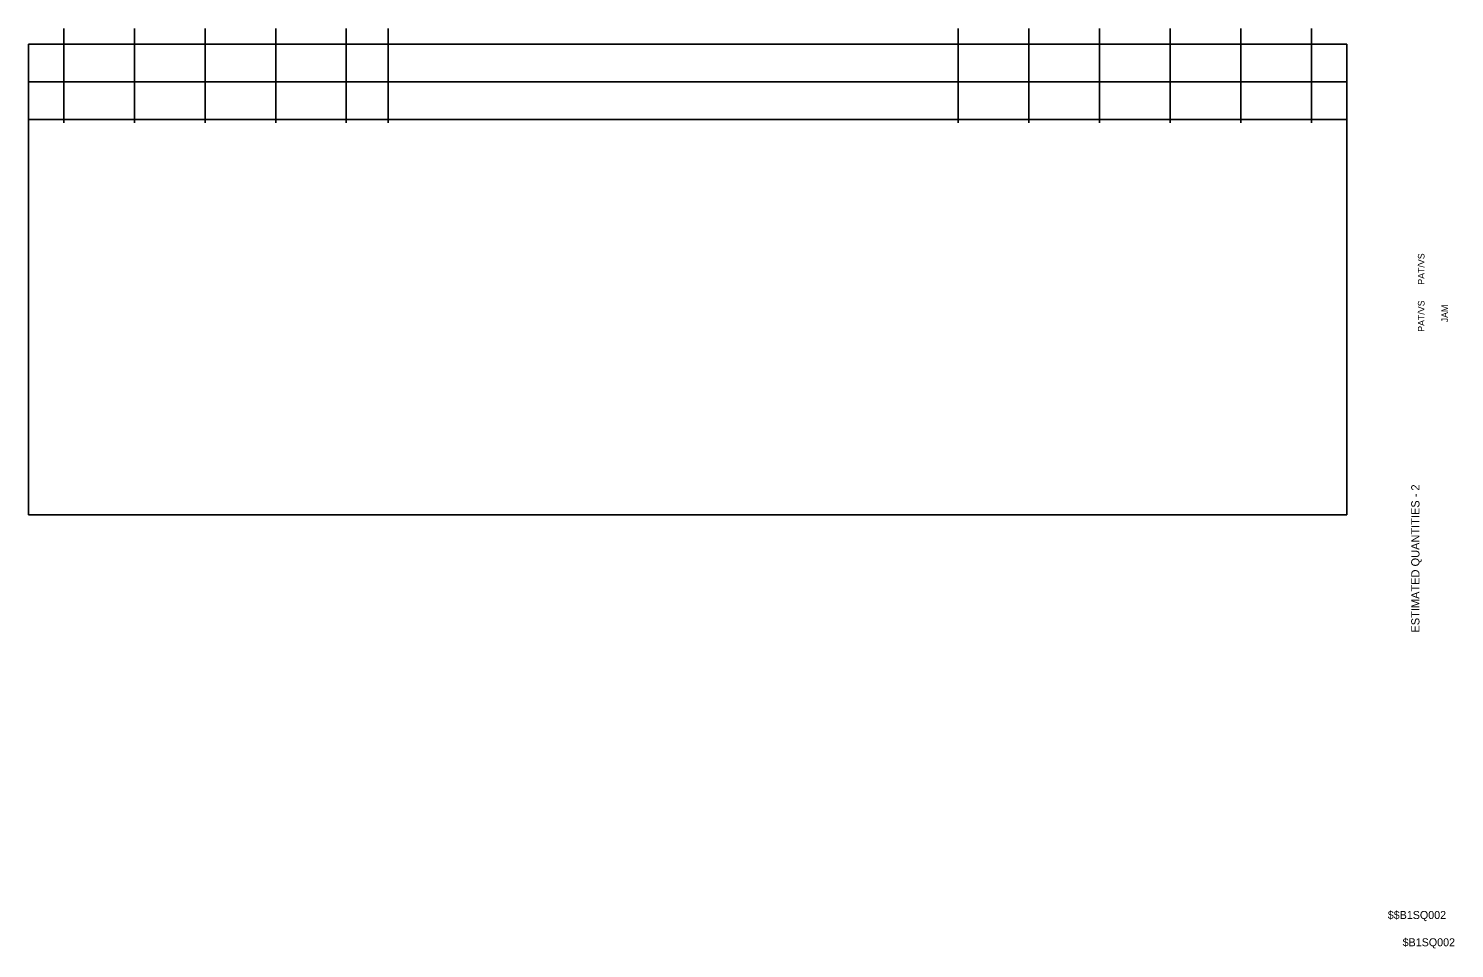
# Model space of a CAD drawing. Extents: x 3.2 to 33.5, y 1 to 20.6.
import ezdxf

# ---------------------------------------------------------------- set-up
doc = ezdxf.new("R2010")
doc.units = 0
for name, color, linetype in [('SC_Scratch1', 7, 'Continuous'), ('SH_Data', 7, 'Continuous'), ('SH_Text', 7, 'Continuous')]:
    doc.layers.add(name, color=color, linetype=linetype)

msp = doc.modelspace()

# ---------------------------------------------------------------- linework, layer by layer
at = {"layer": 'SC_Scratch1'}
for p, q in [((4, 18.58), (4, 20.58)), ((5.5, 18.58), (5.5, 20.58)), ((7, 18.58), (7, 20.58)), ((8.5, 18.58), (8.5, 20.58)), ((10, 18.58), (10, 20.58)), ((10.89, 18.58), (10.89, 20.58)), ((23, 18.58), (23, 20.58)), ((24.5, 18.58), (24.5, 20.58)), ((26, 18.58), (26, 20.58)), ((27.5, 18.58), (27.5, 20.58)), ((29, 18.58), (29, 20.58)), ((30.5, 18.58), (30.5, 20.58))]:
    msp.add_line(p, q, dxfattribs=at)
at = {"layer": 'SH_Text'}
for p, q in [((3.25, 20.25), (31.25, 20.25)), ((3.25, 20.25), (3.25, 10.25)), ((31.25, 20.25), (31.25, 10.25)), ((3.25, 19.45), (31.25, 19.45)), ((3.25, 18.65), (31.25, 18.65)), ((3.25, 10.25), (31.25, 10.25))]:
    msp.add_line(p, q, dxfattribs=at)

# ---------------------------------------------------------------- texts
at = {"layer": 'SH_Data'}
for s, height, p in [('PAT/VS', 0.14, (32.903, 15.138)), ('PAT/VS', 0.14, (32.903, 14.138)), ('JAM', 0.14, (33.403, 14.339)), ('ESTIMATED QUANTITIES - 2', 0.175, (32.796, 7.749))]:
    msp.add_text(s, height=height, rotation=90, dxfattribs=at).set_placement(p)
for s, p in [('$$B1SQ002', (32.123, 1.665)), ('$B1SQ002', (32.439, 1.085))]:
    msp.add_text(s, height=0.17, dxfattribs=at).set_placement(p)

doc.saveas('drawing.dxf')
